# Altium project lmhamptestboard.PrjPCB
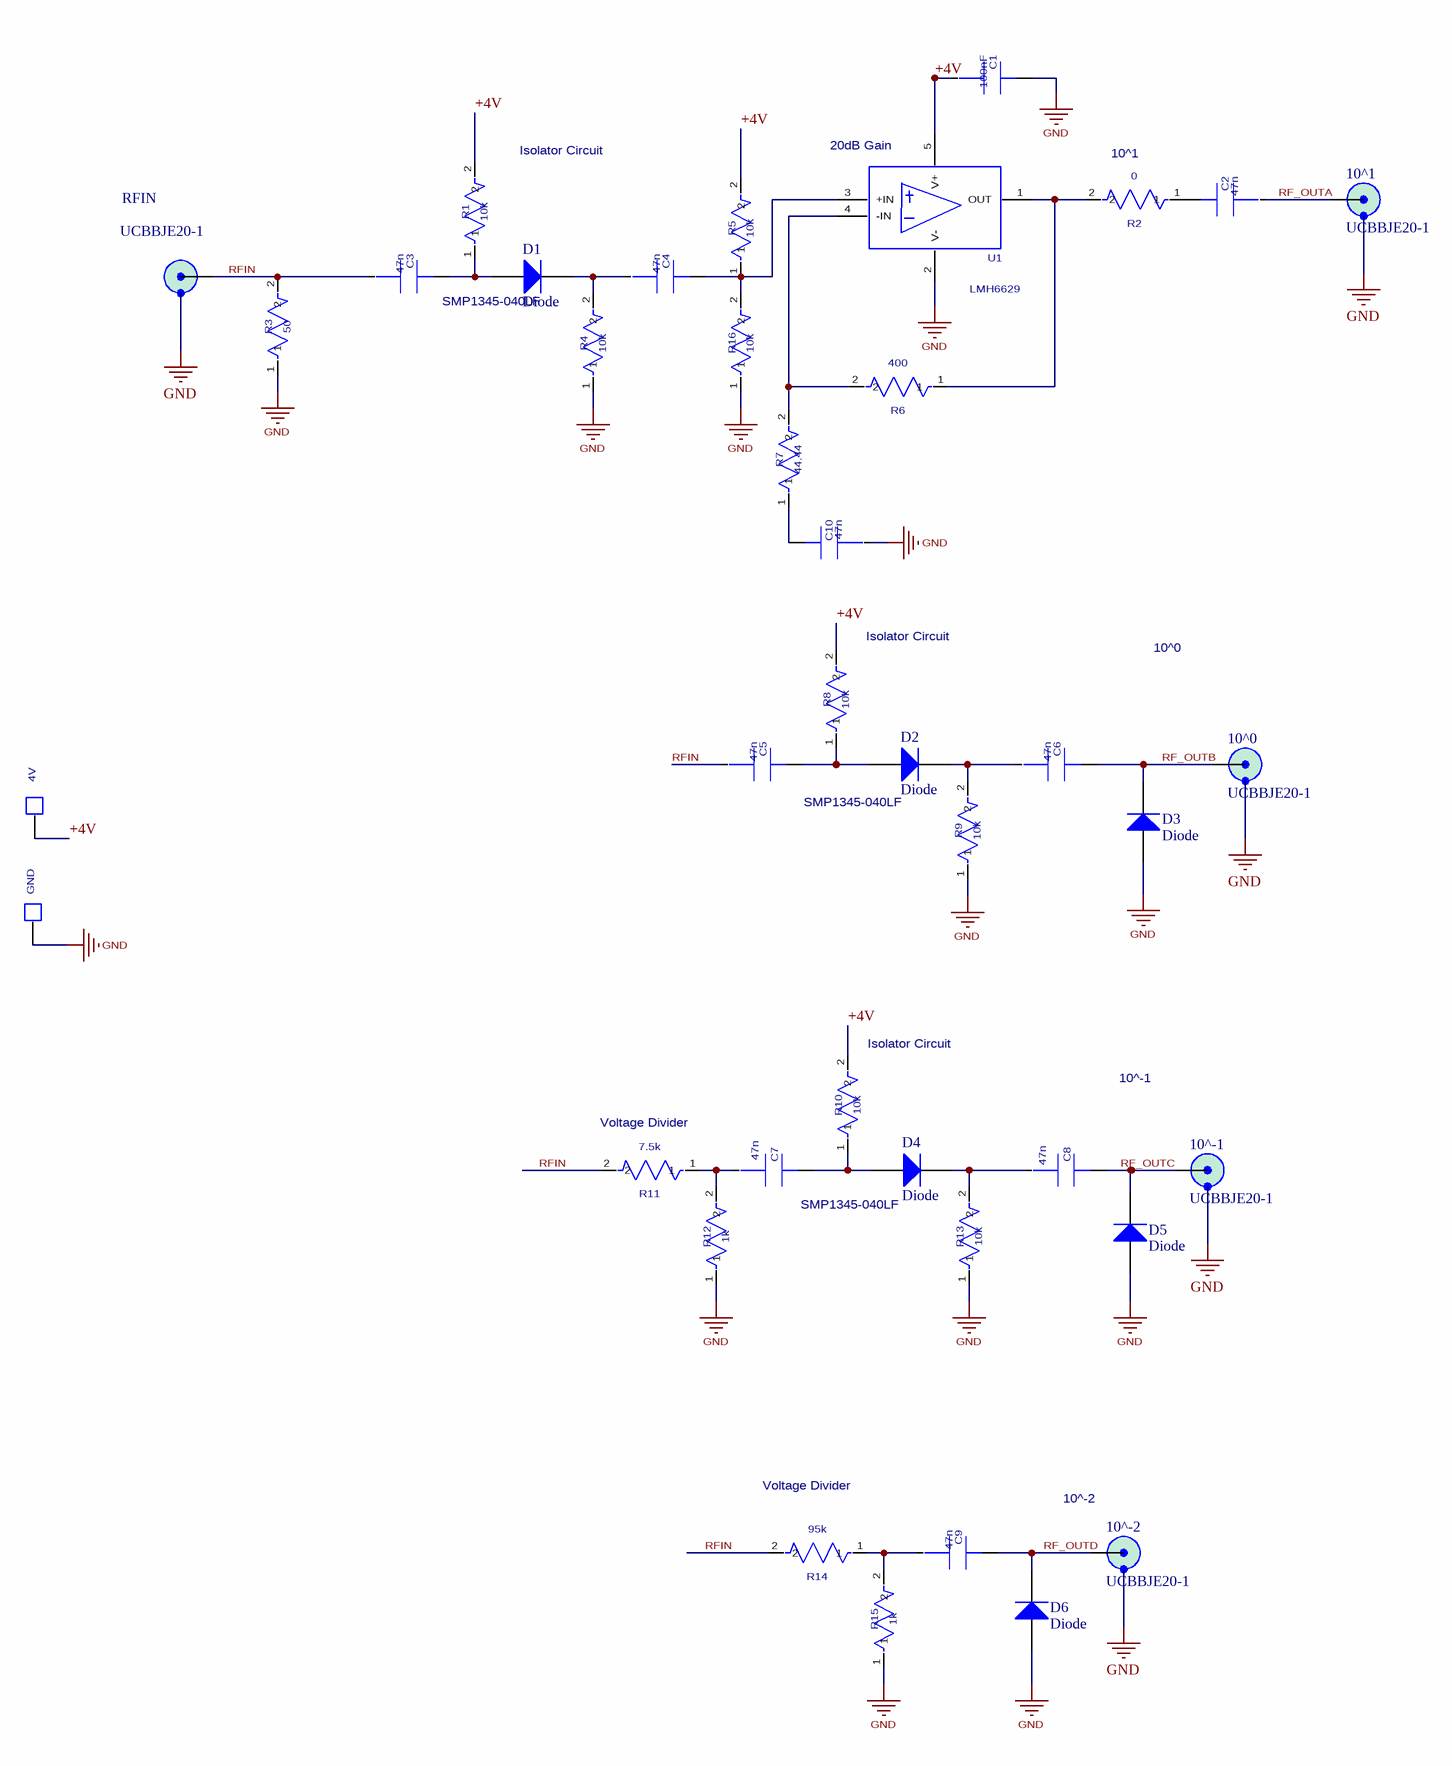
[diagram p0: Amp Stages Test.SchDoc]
1 sheet, 40 parts. Net scope: global (net labels, ports and power ports of the same name join across sheets).
Board file: lmhamptestboard.PcbDoc

## Sheet Amp Stages Test.SchDoc: Title_doc_parameter!
size 401 x 291 mm

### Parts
4V  TEST-POINT-SURFACE-MOUNT  [TPH0.5S]  (value not drawn)
10^0  UCBBJE20-1  [CNSMAPCBEDGE3]
10^1  UCBBJE20-1  [CNSMAPCBEDGE3]
10^-1  UCBBJE20-1  [CNSMAPCBEDGE3]
10^-2  UCBBJE20-1  [CNSMAPCBEDGE3]
C1  value 100nF  [CC0402N1X]  (hidden comment: CAPACITOR-0402)
C2  value 47n  [CC0402N1X]  (hidden comment: CAPACITOR-0402)
C3  value 47n  [CC0402N1X]  (hidden comment: CAPACITOR-0402)
C4  value 47n  [CC0402N1X]  (hidden comment: CAPACITOR-0402)
C5  value 47n  [CC0402N1X]  (hidden comment: CAPACITOR-0402)
C6  value 47n  [CC0402N1X]  (hidden comment: CAPACITOR-0402)
C7  value 47n  [CC0402N1X]  (hidden comment: CAPACITOR-0402)
C8  value 47n  [CC0402N1X]  (hidden comment: CAPACITOR-0402)
C9  value 47n  [CC0402N1X]  (hidden comment: CAPACITOR-0402)
C10  value 47n  [CC0402N1X]  (hidden comment: CAPACITOR-0402)
D1  Diode  [0402-A]
D2  Diode  [0402-A]
D3  Diode  [0402-A]
D4  Diode  [0402-A]
D5  Diode  [0402-A]
D6  Diode  [0402-A]
GND  TEST-POINT-SURFACE-MOUNT  [TPH0.5S]  (value not drawn)
R1  value 10k  [CC0402N1X]  (hidden comment: RES0402)
R2  value 0  [CC0402N1X]  (hidden comment: RES0402)
R3  value 50  [1206]  (hidden comment: RES1206)
R4  value 10k  [CC0402N1X]  (hidden comment: RES0402)
R5  value 10k  [CC0402N1X]  (hidden comment: RES0402)
R6  value 400  [CC0402N1X]  (hidden comment: RES0402)
R7  value 44.44  [CC0402N1X]  (hidden comment: RES0402)
R8  value 10k  [CC0402N1X]  (hidden comment: RES0402)
R9  value 10k  [CC0402N1X]  (hidden comment: RES0402)
R10  value 10k  [CC0402N1X]  (hidden comment: RES0402)
R11  value 7.5k  [CC0402N1X]  (hidden comment: RES0402)
R12  value 1k  [CC0402N1X]  (hidden comment: RES0402)
R13  value 10k  [CC0402N1X]  (hidden comment: RES0402)
R14  value 95k  [CC0402N1X]  (hidden comment: RES0402)
R15  value 1k  [CC0402N1X]  (hidden comment: RES0402)
R16  value 10k  [CC0402N1X]  (hidden comment: RES0402)
RFIN  UCBBJE20-1  [CNSMAPCBEDGE3]
U1  LMH6629  [SOT23-5]

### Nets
GND: 10^0.2 10^1.2 10^-1.2 10^-2.2 C1.2 C10.1 D3.1(A) D5.1(A) D6.1(A) GND.1 R3.1 R4.1 R9.1 R12.1 R13.1 R15.1 R16.1 RFIN.2 U1.2(V-)
+4V: 4V.1 C1.1 R1.2 R5.2 R8.2 R10.2 U1.5(V+)
RF_OUTA: 10^1.1 C2.1
RF_OUTB: 10^0.1 C6.2 D3.2(K)
RF_OUTC: 10^-1.1 C8.2 D5.2(K)
RF_OUTD: 10^-2.1 C9.2 D6.2(K)
RFIN: C3.1 C5.1 R3.2 R11.2 R14.2 RFIN.1
NetC2_2: C2.2 R2.1
NetC3_2: C3.2 D1.1(A) R1.1
NetC4_1: C4.1 D1.2(K) R4.2
NetC4_2: C4.2 R5.1 R16.2 U1.3(+IN)
NetC5_2: C5.2 D2.1(A) R8.1
NetC6_1: C6.1 D2.2(K) R9.2
NetC7_1: C7.1 R11.1 R12.2
NetC7_2: C7.2 D4.1(A) R10.1
NetC8_1: C8.1 D4.2(K) R13.2
NetC9_1: C9.1 R14.1 R15.2
NetC10_2: C10.2 R7.1
NetR2_2: R2.2 R6.1 U1.1(OUT)
NetR6_2: R6.2 R7.2 U1.4(-IN)

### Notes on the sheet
- (near R1) Isolator Circuit
- (near U1) 20dB Gain
- (near R2) 10^1
- SMP1345-040LF
- (near R8) Isolator Circuit
- 10^0
- (near R10) Isolator Circuit
- 10^-1
- (near R11) Voltage Divider
- Voltage Divider
- (near 10^-2) 10^-2

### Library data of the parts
10^0 10^1 10^-1 10^-2 RFIN = UCBBJE20-1: 75R Circuit Board Bulkhead Edge Mount  Coax “BNC” Style Receptacle; Manufacturer: Trompeter; Sort: 610; Tech: THDW
C1-C10 = CAPACITOR-0402: capacitor; Manufacturer #1: IPC SM-782 STD.; Sim.Analog.Order: Model$; PCB DECAL: 0402; Geometry.Height: 1mm
D1-D6 = Diode: Default Diode
R1 R2 R4-R16 = RES0402: SURFACE MOUNT RESISTOR 0.020 X 0.040 INCHES, 1/16W; Manufacturer #1: IPC SM-782 STD.; Sim.Analog.Order: Model$; Sim.Analog.Prefix: R; PCB DECAL: 0402
R3 = RES1206: SURFACE MOUNT RESISTOR 0.062 X 0.126 INCHES, 1/8W; Manufacturer #1: IPC SM-782 STD.; Sim.Analog.Order: Model$; Sim.Analog.Prefix: R
U1 = LMH6624: PCB DECAL: SOT-23-5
